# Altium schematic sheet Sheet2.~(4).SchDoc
size B; SheetNumber: 1; SheetTotal: 1
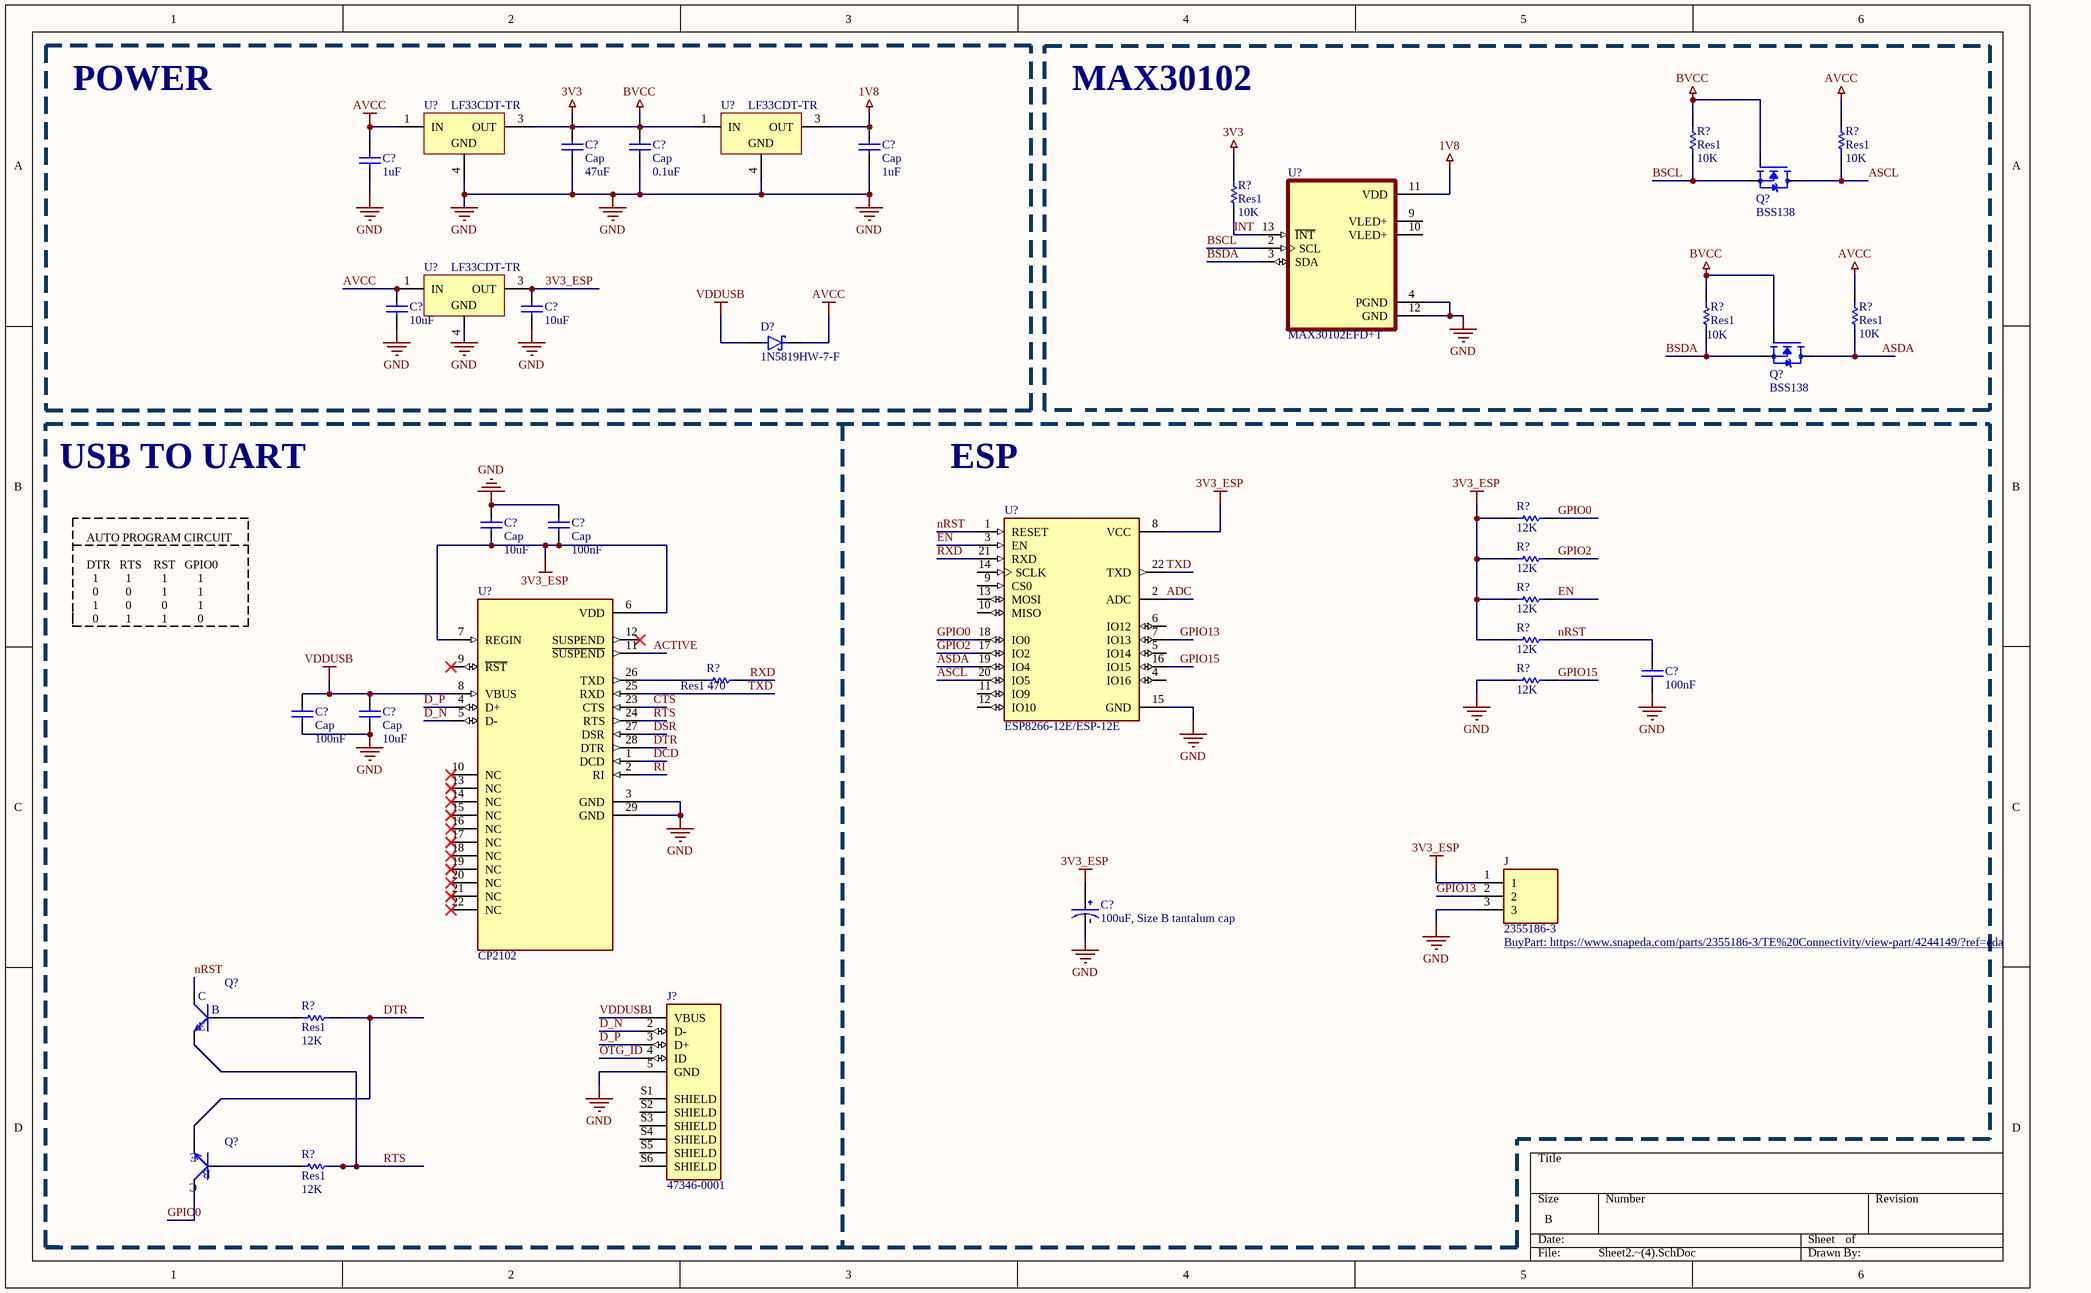
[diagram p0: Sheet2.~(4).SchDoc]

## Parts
(Parts that share a designator on the sheet are numbered #1, #2 ... from top to bottom, then left to right.)
C?#1  Cap  value 47uF  [RAD-0.3]
C?#2  Cap  value 0.1uF  [RAD-0.3]
C?#3  Cap  value 1uF  [RAD-0.3]
C?#4  1uF  [CAP805]
C?#5  10uF  [CAP805]
C?#6  10uF  [CAP805]
C?#7  Cap  value 10uF  [RAD-0.3]
C?#8  Cap  value 100nF  [RAD-0.3]
C?#9  100nF  [CAP805]
C?#10  Cap  value 100nF  [RAD-0.3]
C?#11  Cap  value 10uF  [RAD-0.3]
C?#12  100uF, Size B tantalum cap  [CAPMC6032X260]
D?  1N5819HW-7-F  [SOD3715X145N]
J  2355186-3  [TE_2355186-3]
J?  47346-0001  [MOLEX_47346-0001]
Q?#1  BSS138  [SOT95P240X111-3N]
Q?#2  BSS138  [SOT95P240X111-3N]
Q?#3  SMD-TRANSISTORS-NPN-25V-500MW(SOT-23)  [SOT-23]  (value not drawn)
Q?#4  SMD-TRANSISTORS-NPN-25V-500MW(SOT-23)  [SOT-23]  (value not drawn)
R?#1  Res1  value 10K  [AXIAL-0.3]
R?#2  Res1  value 10K  [AXIAL-0.3]
R?#3  Res1  value 10K  [AXIAL-0.3]
R?#4  Res1  value 10K  [AXIAL-0.3]
R?#5  Res1  value 10K  [AXIAL-0.3]
R?#6  12K  [RES0805]
R?#7  12K  [RES0805]
R?#8  12K  [RES0805]
R?#9  12K  [RES0805]
R?#10  Res1  value 470  [AXIAL-0.3]
R?#11  12K  [RES0805]
R?#12  Res1  value 12K  [AXIAL-0.3]
R?#13  Res1  value 12K  [AXIAL-0.3]
U?#1  LF33CDT-TR  [TO-252_N]
U?#2  LF33CDT-TR  [TO-252_N]
U?#3  MAX30102EFD+T  [XDCR_MAX30101EFD+]
U?#4  LF33CDT-TR  [TO-252_N]
U?#5  ESP8266-12E/ESP-12E  [XCVR_ESP8266-12E/ESP-12E]
U?#6  CP2102  [QFN50P500X500X100-29N]

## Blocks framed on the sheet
POWER: C?#1-C?#6 D? U?#1 U?#2 U?#4

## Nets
1V8: C?#3.2 U?#2.3(OUT) U?#3.11(VDD)
3V3: C?#1.2 C?#2.2 Q?#1.1(G) Q?#2.1(G) R?#1.2 R?#3.2 R?#4.2 U?#1.3(OUT) U?#2.1(IN)  [also labelled BVCC]
3V3_ESP: C?#6.2 C?#7.2 C?#8.2 C?#12.POS J.1 R?#6.1 R?#7.1 R?#8.1 R?#9.1 U?#4.3(OUT) U?#5.8(VCC) U?#6.6(VDD) U?#6.7(REGIN)
AVCC: C?#4.2 C?#5.2 D?.C(K) R?#2.2 R?#5.2 U?#1.1(IN) U?#4.1(IN)
GND: C?#1.1 C?#2.1 C?#3.1 C?#4.1 C?#5.1 C?#6.1 C?#7.1 C?#8.1 C?#9.1 C?#10.1 C?#11.1 C?#12.NEG J.3 J?.5(GND) R?#11.1 U?#1.4(GND) U?#2.4(GND) U?#3.4(PGND) U?#3.12(GND) U?#4.4(GND) U?#5.15(GND) U?#6.3(GND) U?#6.29(GND)
VDDUSB: C?#10.2 C?#11.2 D?.A J?.1(VBUS) U?#6.8(VBUS)
ACTIVE: U?#6.11(~{SUSPEND})
ADC: U?#5.2(ADC)
ASCL: Q?#1.3(D) R?#2.1 U?#5.20(IO5)
ASDA: Q?#2.3(D) R?#5.1 U?#5.19(IO4)
BSCL: Q?#1.2(S) R?#1.1 U?#3.2(SCL)
BSDA: Q?#2.2(S) R?#4.1 U?#3.3(SDA)
CTS: U?#6.23(CTS)
D_N: J?.2(D-) U?#6.5(D-)
D_P: J?.3(D+) U?#6.4(D+)
DCD: U?#6.1(DCD)
DSR: U?#6.27(DSR)
DTR: Q?#4.2(E) R?#12.2 U?#6.28(DTR)
EN: R?#8.2 U?#5.3(EN)
GPIO0: Q?#4.3(C) R?#6.2 U?#5.18(IO0)
GPIO2: R?#7.2 U?#5.17(IO2)
GPIO13: J.2 U?#5.7(IO13)
GPIO15: R?#11.2 U?#5.16(IO15)
INT: R?#3.1 U?#3.13(~{INT})
nRST: C?#9.2 Q?#3.3(C) R?#9.2 U?#5.1(RESET)
OTG_ID: J?.4(ID)
RI: U?#6.2(RI)
RTS: Q?#3.2(E) R?#13.2 U?#6.24(RTS)
RXD: R?#10.2 U?#5.21(RXD)
TXD: U?#5.22(TXD) U?#6.25(RXD)
NetQ?#3_1: Q?#3.1(B) R?#12.1
NetQ?#4_1: Q?#4.1(B) R?#13.1
NetR?#10_1: R?#10.1 U?#6.26(TXD)

Not connected (* = marked no-connect by the designer): J? S1(SHIELD) S2(SHIELD) S3(SHIELD) S4(SHIELD) S5(SHIELD) S6(SHIELD); U?#3 9(VLED+) 10(VLED+); U?#5 4(IO16) 5(IO14) 6(IO12) 9(CS0) 10(MISO) 11(IO9) 12(IO10) 13(MOSI) 14(SCLK); U?#6 9(~{RST})* 10(NC)* 12(SUSPEND)* 13(NC)* 14(NC)* 15(NC)* 16(NC)* 17(NC)* 18(NC)* 19(NC)* 20(NC)* 21(NC)* 22(NC)*

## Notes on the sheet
- MAX30102
- USB TO UART
- ESP
- AUTO PROGRAM CIRCUIT
  DTR   RTS    RST   GPIO0
  1         1          1          1
  0         0          1          1
  1         0          0          1
  0         1          1          0

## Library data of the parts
C?#1-C?#3 C?#7 C?#8 C?#10 C?#11 = Cap: Capacitor
C?#4 = CAP SMD PACKAGE: TOTAL CAPACITOR SMD PACK; Designer: Abbas Basereh; Desc.: CAP SMD TOTAL PACKAGES; VALUE: 100nF
C?#5 C?#6 C?#9 = CAP SMD PACKAGE: TOTAL CAPACITOR SMD PACK; Designer: Abbas Basereh; Desc.: CAP SMD TOTAL PACKAGES
C?#12 = TAJC107K016RNJ: 100µF Molded Tantalum Capacitors 16V 2312 _6032 Metric_ 1Ohm; MF: AVX Interconnect / Elco
D? = 1N5819HW-7-F: Diode Schottky 40 V 1A Surface Mount SOD-123; MF: Diodes Inc.
J = 2355186-3: Pin 3P,2MM,BRK HDR,SRVT,2.8,0.76AU,BOX 3 POS; MF: TE Connectivity
J? = 47346-0001: USB - micro B USB 2.0 Receptacle Connector 5 Position Surface Mount, Right Angle; MF: Molex
Q?#1 Q?#2 = BSS138: N-Channel 50 V 220mA (Ta) 350mW (Ta) Surface Mount SOT-23-3; MF: onsemi
Q?#3 Q?#4 = SMD-TRANSISTORS-NPN-25V-500MW(SOT-23): Bipolar (BJT) Transistor NPN 25 V 500 mA 150MHz 300 mW Surface Mount SOT-23; MF: UMW; MP: S8050
R?#1-R?#5 R?#10 R?#12 R?#13 = Res1: Resistor
R?#6-R?#9 R?#11 = RES SMD PACKAGE: TOTAL SMD RESISTOR PACK; Designer: Abbas Basereh; Desc.: RES SMD PAKAGES
U?#1 U?#2 U?#4 = LF33CDT-TR: 500mA, Very Low Drop (0.45V) Voltage Regulator, 3.3V, 3-Pin DPAK, Tape and Reel
U?#3 = MAX30102EFD+T: Pulse Oximeter and Heart Rate Sensor Digital Output; MF: Maxim Integrated Products
U?#5 = ESP8266-12E/ESP-12E: This WiFi module has a 32-bit MCU micro and clock speeds supporting 80 MHz or 160 MHz. Supports the RTOS and integrated Wi-Fi MAC/BB/RF/PA/LNA, and has an on-board antenna.; MF: AI-Thinker
U?#6 = CP2102: CP2102N USB 2.0 to UART (RS232) Bridge Interface Evaluation Board; MF: Silicon Labs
